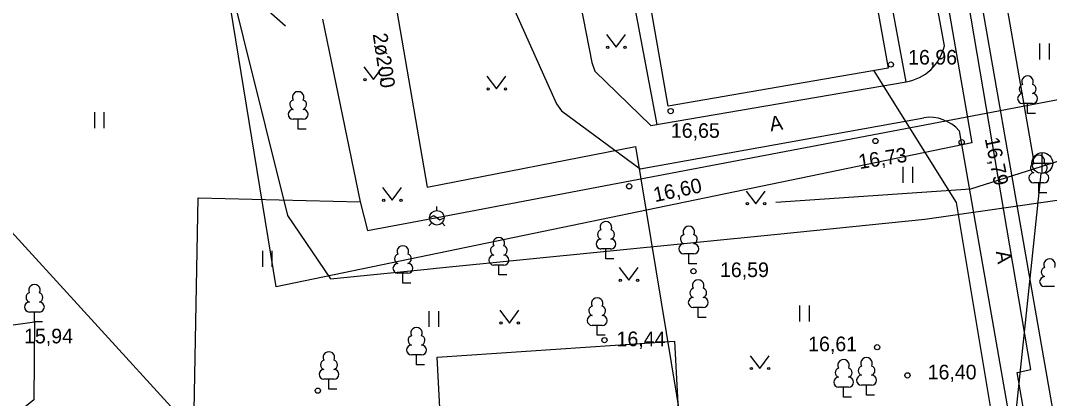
# Model space of a CAD drawing. Extents: x 713540 to 713867, y 6589774 to 6590061.
# Drawn here: x 713651.49 to 713700.77, y 6589826.2 to 6589844.3 of the extents above; entities that cross this region are included whole.
import ezdxf

# ---------------------------------------------------------------- set-up
doc = ezdxf.new("R2010")
doc.units = 0
for name, color, linetype in [('HALJASTUS', 7, 'Continuous'), ('HOONE', 7, 'Continuous'), ('HOONEDET', 7, 'Continuous'), ('KKAEV', 7, 'Continuous'), ('KORGUS', 7, 'Continuous'), ('KTRASS', 7, 'Continuous'), ('MPKAABEL', 7, 'Continuous'), ('PUU', 7, 'Continuous'), ('SITRASS', 7, 'Continuous'), ('SKTRASS', 7, 'Continuous'), ('TEE', 7, 'Continuous'), ('TORU NR', 7, 'Continuous'), ('TTRASS', 7, 'Continuous'), ('VTRASS', 7, 'Continuous'), ('Слой 1', 7, 'Continuous')]:
    doc.layers.add(name, color=color, linetype=linetype)

msp = doc.modelspace()

# ---------------------------------------------------------------- linework, layer by layer
at = {"layer": 'HALJASTUS'}
for p, q in [((713679.557, 6589843.627), (713680.02, 6589843.02)), ((713680.02, 6589843.02), (713680.466, 6589843.627)), ((713700.3, 6589843.201), (713700.3, 6589842.44)), ((713700.755, 6589843.201), (713700.755, 6589842.44)), ((713667.927, 6589842.077), (713668.39, 6589841.47)), ((713668.39, 6589841.47), (713668.836, 6589842.077)), ((713673.827, 6589841.627), (713674.29, 6589841.02)), ((713674.29, 6589841.02), (713674.736, 6589841.627)), ((713655.026, 6589839.902), (713655.026, 6589839.141)), ((713655.481, 6589839.902), (713655.481, 6589839.141)), ((713693.756, 6589837.287), (713693.756, 6589836.526)), ((713694.211, 6589837.287), (713694.211, 6589836.526)), ((713668.827, 6589836.297), (713669.29, 6589835.69)), ((713669.29, 6589835.69), (713669.736, 6589836.297)), ((713686.247, 6589836.127), (713686.71, 6589835.52)), ((713686.71, 6589835.52), (713687.156, 6589836.127)), ((713663.075, 6589833.26), (713663.075, 6589832.498)), ((713663.53, 6589833.26), (713663.53, 6589832.498)), ((713680.157, 6589832.467), (713680.62, 6589831.86)), ((713680.62, 6589831.86), (713681.066, 6589832.467)), ((713688.809, 6589830.644), (713688.809, 6589829.883)), ((713689.264, 6589830.644), (713689.264, 6589829.883)), ((713671.05, 6589830.381), (713671.05, 6589829.62)), ((713671.505, 6589830.381), (713671.505, 6589829.62)), ((713674.447, 6589830.417), (713674.91, 6589829.81)), ((713674.91, 6589829.81), (713675.356, 6589830.417)), ((713686.437, 6589828.237), (713686.9, 6589827.63)), ((713686.9, 6589827.63), (713687.346, 6589828.237))]:
    msp.add_line(p, q, dxfattribs=at)
msp.add_lwpolyline([(713652.155, 6589829.862), (713652.122, 6589826.127), (713646.843, 6589821.832), (713647.493, 6589829.212), (713652.155, 6589829.862)], dxfattribs=at)
for centre in [(713679.619, 6589843.02), (713680.448, 6589843.02), (713667.989, 6589841.47), (713668.818, 6589841.47), (713673.889, 6589841.02), (713674.718, 6589841.02), (713668.889, 6589835.69), (713669.718, 6589835.69), (713686.309, 6589835.52), (713687.138, 6589835.52), (713680.219, 6589831.86), (713681.048, 6589831.86), (713674.509, 6589829.81), (713675.338, 6589829.81), (713686.499, 6589827.63), (713687.328, 6589827.63)]:
    msp.add_circle(centre, 0.055, dxfattribs=at)
at = {"layer": 'HOONE'}
for p, q in [((713671.43, 6589835.2), (713671.43, 6589835.397)), ((713671.08, 6589834.848), (713671.291, 6589834.954)), ((713671.291, 6589834.954), (713671.569, 6589834.746)), ((713671.183, 6589834.603), (713671.043, 6589834.463)), ((713671.569, 6589834.746), (713671.78, 6589834.852)), ((713671.677, 6589834.603), (713671.817, 6589834.463))]:
    msp.add_line(p, q, dxfattribs=at)
for points in [[(713670.244, 6589868.298), (713687.74, 6589871.45), (713693.041, 6589842.02), (713682.51, 6589840.189), (713679.207, 6589859.1), (713672.137, 6589857.822), (713670.244, 6589868.298)], [(713665.96, 6589844.37), (713667.76, 6589835.61)], [(713671.44, 6589834.87), (713687.15, 6589837.855), (713710.253, 6589842.245), (713710.463, 6589842.286), (713715.96, 6589843.33), (713717, 6589843.42)], [(713659.4, 6589804.37), (713660, 6589835.81), (713667.76, 6589835.61)], [(713667.76, 6589835.61), (713668.11, 6589834.24), (713671.44, 6589834.87)]]:
    msp.add_lwpolyline(points, dxfattribs=at)
msp.add_circle((713671.43, 6589834.85), 0.35, dxfattribs=at)
at = {"layer": 'HOONEDET'}
msp.add_lwpolyline([(713681.98, 6589839.324), (713680.57, 6589846.86)], dxfattribs=at)
at = {"layer": 'KKAEV'}
for p, q in [((713700.431, 6589836.971), (713700.431, 6589837.971)), ((713699.931, 6589837.471), (713700.931, 6589837.471))]:
    msp.add_line(p, q, dxfattribs=at)
msp.add_circle((713700.431, 6589837.471), 0.5, dxfattribs=at)
at = {"layer": 'KORGUS'}
for centre in [(713693.18, 6589842.19), (713682.63, 6589839.96), (713692.44, 6589838.53), (713696.57, 6589838.47), (713680.64, 6589836.36), (713683.72, 6589832.29), (713679.46, 6589828.99), (713692.52, 6589828.65), (713693.97, 6589827.3), (713665.73, 6589826.57)]:
    msp.add_circle(centre, 0.125, dxfattribs=at)
at = {"layer": 'KTRASS'}
msp.add_line((713647.455, 6589838.108), (713679.09, 6589803.497), dxfattribs=at)
at = {"layer": 'MPKAABEL'}
for points in [[(713621.405, 6589921.156), (713617.009, 6589909.766), (713616.379, 6589906.228), (713617.893, 6589905.104), (713618.264, 6589904.829), (713628.654, 6589899.391), (713631.248, 6589897.024), (713632.991, 6589885.086), (713637.163, 6589875.703), (713640.145, 6589871.993), (713646.211, 6589866.173), (713649.924, 6589862.847), (713657.342, 6589851.294), (713662.171, 6589845.836), (713664.179, 6589844.049)], [(713710.985, 6589839.36), (713710.816, 6589839.338), (713702.066, 6589837.833), (713696.99, 6589836.226), (713687.666, 6589835.577)]]:
    msp.add_lwpolyline(points, dxfattribs=at)
at = {"layer": 'PUU'}
for p, q in [((713699.967, 6589840.324), (713699.487, 6589840.324)), ((713699.727, 6589839.849), (713699.727, 6589840.324)), ((713700.107, 6589839.849), (713699.727, 6589839.849)), ((713665.027, 6589839.569), (713664.547, 6589839.569)), ((713664.787, 6589839.094), (713664.787, 6589839.569)), ((713665.167, 6589839.094), (713664.787, 6589839.094)), ((713700.506, 6589836.525), (713700.026, 6589836.525)), ((713700.266, 6589836.05), (713700.266, 6589836.525)), ((713700.646, 6589836.05), (713700.266, 6589836.05)), ((713679.77, 6589833.355), (713679.29, 6589833.355)), ((713679.53, 6589832.88), (713679.53, 6589833.355)), ((713683.74, 6589833.125), (713683.26, 6589833.125)), ((713683.5, 6589832.65), (713683.5, 6589833.125)), ((713674.64, 6589832.585), (713674.16, 6589832.585)), ((713674.4, 6589832.11), (713674.4, 6589832.585)), ((713679.91, 6589832.88), (713679.53, 6589832.88)), ((713683.88, 6589832.65), (713683.5, 6589832.65)), ((713670.043, 6589832.191), (713669.563, 6589832.191)), ((713669.803, 6589831.716), (713669.803, 6589832.191)), ((713674.78, 6589832.11), (713674.4, 6589832.11)), ((713670.183, 6589831.716), (713669.803, 6589831.716)), ((713701.02, 6589831.555), (713700.54, 6589831.555)), ((713684.19, 6589830.555), (713683.71, 6589830.555)), ((713683.95, 6589830.08), (713683.95, 6589830.555)), ((713652.395, 6589830.337), (713651.915, 6589830.337)), ((713652.155, 6589829.862), (713652.155, 6589830.337)), ((713684.33, 6589830.08), (713683.95, 6589830.08)), ((713652.535, 6589829.862), (713652.155, 6589829.862)), ((713679.35, 6589829.695), (713678.87, 6589829.695)), ((713679.11, 6589829.22), (713679.11, 6589829.695)), ((713679.49, 6589829.22), (713679.11, 6589829.22)), ((713670.696, 6589828.278), (713670.216, 6589828.278)), ((713670.456, 6589827.803), (713670.456, 6589828.278)), ((713670.836, 6589827.803), (713670.456, 6589827.803)), ((713666.501, 6589827.114), (713666.021, 6589827.114)), ((713666.261, 6589826.639), (713666.261, 6589827.114)), ((713666.641, 6589826.639), (713666.261, 6589826.639)), ((713691.153, 6589826.736), (713690.673, 6589826.736)), ((713690.913, 6589826.261), (713690.913, 6589826.736)), ((713692.253, 6589826.831), (713691.773, 6589826.831)), ((713692.013, 6589826.356), (713692.013, 6589826.831)), ((713691.293, 6589826.261), (713690.913, 6589826.261)), ((713692.393, 6589826.356), (713692.013, 6589826.356))]:
    msp.add_line(p, q, dxfattribs=at)
for centre, radius, start, end in [((713699.727, 6589841.369), 0.277, 332.5799, 207.4201), ((713664.787, 6589840.614), 0.277, 332.5799, 207.4201), ((713699.489, 6589840.561), 0.238, 90.0016, 269.3953), ((713699.557, 6589841.022), 0.233, 109.0217, 253.1415), ((713699.897, 6589841.022), 0.233, 286.8508, 70.9859), ((713699.964, 6589840.561), 0.238, 270.6047, 89.9984), ((713664.617, 6589840.266), 0.233, 109.0217, 253.1415), ((713664.957, 6589840.266), 0.233, 286.8508, 70.9859), ((713664.549, 6589839.806), 0.238, 90.0016, 269.3953), ((713665.024, 6589839.806), 0.238, 270.6047, 89.9984), ((713700.266, 6589837.57), 0.277, 332.5799, 207.4201), ((713700.096, 6589837.222), 0.233, 109.0217, 253.1415), ((713700.436, 6589837.222), 0.233, 286.8508, 70.9859), ((713700.028, 6589836.762), 0.238, 90.0016, 269.3953), ((713700.503, 6589836.762), 0.238, 270.6047, 89.9984), ((713679.53, 6589834.4), 0.277, 332.5799, 207.4201), ((713683.5, 6589834.17), 0.277, 332.5799, 207.4201), ((713674.4, 6589833.63), 0.277, 332.5799, 207.4201), ((713679.36, 6589834.053), 0.233, 109.0217, 253.1415), ((713679.7, 6589834.053), 0.233, 286.8508, 70.9859), ((713683.33, 6589833.823), 0.233, 109.0217, 253.1415), ((713683.67, 6589833.823), 0.233, 286.8508, 70.9859), ((713669.803, 6589833.236), 0.277, 332.5799, 207.4201), ((713674.23, 6589833.283), 0.233, 109.0217, 253.1415), ((713674.57, 6589833.283), 0.233, 286.8508, 70.9859), ((713679.293, 6589833.592), 0.238, 90.0016, 269.3953), ((713679.767, 6589833.592), 0.238, 270.6047, 89.9984), ((713683.263, 6589833.362), 0.238, 90.0016, 269.3953), ((713683.737, 6589833.362), 0.238, 270.6047, 89.9984), ((713669.633, 6589832.888), 0.233, 109.0217, 253.1415), ((713669.973, 6589832.888), 0.233, 286.8508, 70.9859), ((713674.163, 6589832.822), 0.238, 90.0016, 269.3953), ((713674.637, 6589832.822), 0.238, 270.6047, 89.9984), ((713669.566, 6589832.428), 0.238, 90.0016, 269.3953), ((713670.041, 6589832.428), 0.238, 270.6047, 89.9984), ((713700.61, 6589832.253), 0.233, 109.0217, 253.1415), ((713700.78, 6589832.6), 0.277, 332.5799, 207.4201), ((713700.543, 6589831.792), 0.238, 90.0016, 269.3953), ((713652.155, 6589831.382), 0.277, 332.5799, 207.4201), ((713683.78, 6589831.253), 0.233, 109.0217, 253.1415), ((713683.95, 6589831.6), 0.277, 332.5799, 207.4201), ((713684.12, 6589831.253), 0.233, 286.8508, 70.9859), ((713651.985, 6589831.035), 0.233, 109.0217, 253.1415), ((713652.325, 6589831.035), 0.233, 286.8508, 70.9859), ((713679.11, 6589830.74), 0.277, 332.5799, 207.4201), ((713683.713, 6589830.792), 0.238, 90.0016, 269.3953), ((713684.187, 6589830.792), 0.238, 270.6047, 89.9984), ((713651.917, 6589830.575), 0.238, 90.0016, 269.3953), ((713652.392, 6589830.575), 0.238, 270.6047, 89.9984), ((713678.94, 6589830.393), 0.233, 109.0217, 253.1415), ((713679.28, 6589830.393), 0.233, 286.8508, 70.9859), ((713678.873, 6589829.932), 0.238, 90.0016, 269.3953), ((713679.347, 6589829.932), 0.238, 270.6047, 89.9984), ((713670.456, 6589829.323), 0.277, 332.5799, 207.4201), ((713670.286, 6589828.976), 0.233, 109.0217, 253.1415), ((713670.626, 6589828.976), 0.233, 286.8508, 70.9859), ((713670.218, 6589828.516), 0.238, 90.0016, 269.3953), ((713670.693, 6589828.516), 0.238, 270.6047, 89.9984), ((713666.091, 6589827.811), 0.233, 109.0217, 253.1415), ((713666.261, 6589828.159), 0.277, 332.5799, 207.4201), ((713666.431, 6589827.811), 0.233, 286.8508, 70.9859), ((713690.913, 6589827.781), 0.277, 332.5799, 207.4201), ((713692.013, 6589827.876), 0.277, 332.5799, 207.4201), ((713666.024, 6589827.351), 0.238, 90.0016, 269.3953), ((713666.499, 6589827.351), 0.238, 270.6047, 89.9984), ((713690.743, 6589827.433), 0.233, 109.0217, 253.1415), ((713691.083, 6589827.433), 0.233, 286.8508, 70.9859), ((713691.843, 6589827.529), 0.233, 109.0217, 253.1415), ((713692.183, 6589827.529), 0.233, 286.8508, 70.9859), ((713690.676, 6589826.973), 0.238, 90.0016, 269.3953), ((713691.151, 6589826.973), 0.238, 270.6047, 89.9984), ((713691.775, 6589827.068), 0.238, 90.0016, 269.3953), ((713692.25, 6589827.068), 0.238, 270.6047, 89.9984)]:
    msp.add_arc(centre, radius, start, end, dxfattribs=at)
at = {"layer": 'SITRASS'}
for points in [[(713622.526, 6589942.802), (713625.02, 6589914.21), (713630.01, 6589903.07), (713639.36, 6589886.76), (713642.3, 6589872.04), (713652.19, 6589865.47), (713653.052, 6589864.917), (713657.52, 6589862.05), (713661.076, 6589847.8), (713664.28, 6589834.96), (713666.33, 6589831.93), (713670.966, 6589832.394), (713671.39, 6589832.436), (713687.742, 6589834.073), (713694.81, 6589834.78), (713711.155, 6589837.134), (713711.376, 6589837.166), (713715.85, 6589837.81)], [(713692.355, 6589841.896), (713696.3, 6589835.59), (713698.99, 6589819.49), (713700.82, 6589810.63), (713702.44, 6589801.79), (713704.26, 6589791.98), (713706.2, 6589780.63), (713707.441, 6589774.068)]]:
    msp.add_lwpolyline(points, dxfattribs=at)
at = {"layer": 'SKTRASS'}
for points in [[(713693.835, 6589873.124), (713699.989, 6589837.705)], [(713697.172, 6589806.387), (713700.379, 6589836.974)]]:
    msp.add_lwpolyline(points, dxfattribs=at)
at = {"layer": 'TEE'}
for points in [[(713704.07, 6589807.784), (713692.349, 6589874.816)], [(713695.743, 6589843.086), (713689.956, 6589874.556)], [(713693.906, 6589841.364), (713688.181, 6589872.289), (713669.34, 6589868.95)], [(713604.7, 6589841.34), (713603.88, 6589839.2), (713609.91, 6589836.82), (713613.97, 6589847.02), (713617.324, 6589854.463), (713620.034, 6589860.662), (713622.012, 6589862.139), (713624.588, 6589862.589), (713636.035, 6589864.696), (713648.598, 6589866.836), (713651.744, 6589867.418), (713666.405, 6589870.131), (713667.395, 6589870.314), (713668.241, 6589865.803), (713669.69, 6589856.43), (713672.05, 6589851.73), (713677.154, 6589840.312), (713677.401, 6589839.977), (713681.17, 6589837.189), (713694.749, 6589839.642)], [(713648.598, 6589866.836), (713651.744, 6589867.418), (713666.405, 6589870.131), (713667.395, 6589870.314), (713668.241, 6589865.803), (713669.69, 6589856.43), (713672.05, 6589851.73), (713677.154, 6589840.312), (713677.401, 6589839.977), (713681.17, 6589837.189), (713694.749, 6589839.642)], [(713678.59, 6589846.49), (713678.18, 6589845.73), (713678.852, 6589842.282), (713678.998, 6589841.866), (713681.686, 6589839.274), (713693.906, 6589841.364)], [(713696.453, 6589839.015), (713701.863, 6589808.006), (713701.336, 6589806.867)], [(713682.821, 6589828.937), (713683.689, 6589812.444), (713672.306, 6589811.743), (713671.438, 6589828.172), (713682.821, 6589828.937)]]:
    msp.add_lwpolyline(points, dxfattribs=at)
for centre, radius, start, end in [((713693.554, 6589843.58), 2.243, 279.0063, 347.2959), ((713695.035, 6589837.79), 1.874, 40.8397, 98.7732)]:
    msp.add_arc(centre, radius, start, end, dxfattribs=at)
at = {"layer": 'TTRASS'}
msp.add_lwpolyline([(713668.38, 6589851.34), (713670.97, 6589836.31), (713680.94, 6589838.27), (713684.857, 6589814.536)], dxfattribs=at)
at = {"layer": 'VTRASS'}
msp.add_lwpolyline([(713708.725, 6589774.068), (713707.065, 6589783.601), (713705.018, 6589794.55), (713701.84, 6589812.321), (713699.235, 6589827.436), (713699.875, 6589827.579), (713696.888, 6589845.261), (713694.289, 6589860.829), (713691.539, 6589877.243), (713690.275, 6589883.906), (713690.135, 6589884.996), (713689.231, 6589889.843), (713687.737, 6589897.698), (713684.897, 6589913.25), (713684.491, 6589918.952), (713684.308, 6589921.181)], dxfattribs=at)
at = {"layer": 'Слой 1'}
msp.add_lwpolyline([(713697.06, 6589838.44), (713663.74, 6589831.54), (713657.67, 6589868.71), (713657.78, 6589870.72), (713690.33, 6589877.18)], close=True, dxfattribs=at)

# ---------------------------------------------------------------- texts
at = {"layer": 'KORGUS'}
for s, p in [('16,96', (713694.005, 6589842.19)), ('16,65', (713682.641, 6589838.68)), ('16,59', (713684.992, 6589832.01)), ('15,94', (713651.658, 6589828.835)), ('16,44', (713680.039, 6589828.7)), ('16,61', (713689.217, 6589828.46)), ('16,40', (713694.94, 6589827.11))]:
    msp.add_text(s, height=0.7, dxfattribs=at).set_placement(p)
for s, rotation, p in [('16,79', 281.653, (713697.67, 6589838.638)), ('16,73', 8.8157, (713691.679, 6589837.181)), ('16,60', 11.9761, (713681.879, 6589835.597))]:
    msp.add_text(s, height=0.7, rotation=rotation, dxfattribs=at).set_placement(p)
at = {"layer": 'TEE'}
for rotation, p in [(8.784, (713687.422, 6589838.987)), (279.0613, (713698.205, 6589833.229))]:
    msp.add_text('A', height=0.7, rotation=rotation, dxfattribs=at).set_placement(p)
at = {"layer": 'TORU NR'}
msp.add_text('2ø200', height=0.7, rotation=278.6913, dxfattribs=at).set_placement((713668.355, 6589843.648))

doc.saveas('drawing.dxf')
